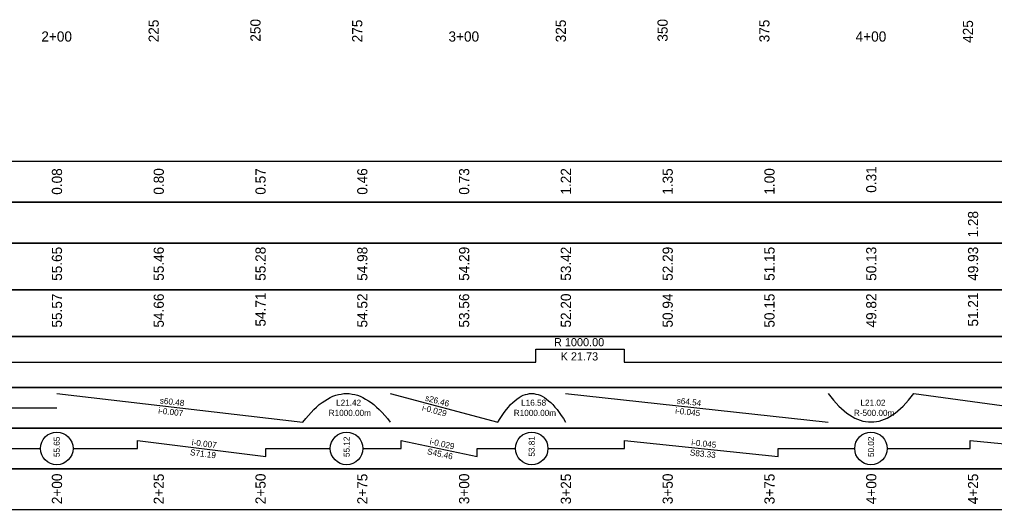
# Model space of a CAD drawing. Extents: x 655100 to 703495, y 6445581 to 6476602.
# Drawn here: x 669500.1 to 669739.6, y 6465749.1 to 6465869.5 of the extents above; entities that cross this region are included whole.
import ezdxf

# ---------------------------------------------------------------- set-up
doc = ezdxf.new("R2010")
doc.units = 0
for name, color, linetype in [('54', 7, 'Continuous'), ('Profile', 7, 'Continuous'), ('Profile Annotation', 7, 'Continuous'), ('Prop_Benching', 7, 'Continuous')]:
    doc.layers.add(name, color=color, linetype=linetype)

msp = doc.modelspace()

# ---------------------------------------------------------------- linework, layer by layer
at = {"layer": '54'}
for points in [[(669299.3, 6465824.57), (670219.3, 6465824.57), (670219.3, 6465834.57), (669299.3, 6465834.57)], [(669299.3, 6465814.57), (670219.3, 6465814.57), (670219.3, 6465824.57), (669299.3, 6465824.57)], [(669299.3, 6465803.07), (670219.3, 6465803.07), (670219.3, 6465814.57), (669299.3, 6465814.57)], [(669299.3, 6465791.57), (670219.3, 6465791.57), (670219.3, 6465803.07), (669299.3, 6465803.07)], [(669299.3, 6465779.07), (670219.3, 6465779.07), (670219.3, 6465791.57), (669299.3, 6465791.57)], [(669299.3, 6465769.07), (670219.3, 6465769.07), (670219.3, 6465779.07), (669299.3, 6465779.07)], [(669299.3, 6465759.07), (670219.3, 6465759.07), (670219.3, 6465769.07), (669299.3, 6465769.07)], [(669299.3, 6465749.07), (670219.3, 6465749.07), (670219.3, 6465759.07), (669299.3, 6465759.07)]]:
    msp.add_lwpolyline(points, close=True, dxfattribs=at)
for points in [[(669509.3, 6465834.57), (669509.3, 6465834.57)], [(669534.3, 6465834.57), (669534.3, 6465834.57)], [(669559.3, 6465834.57), (669559.3, 6465834.57)], [(669584.3, 6465834.57), (669584.3, 6465834.57)], [(669609.3, 6465834.57), (669609.3, 6465834.57)], [(669634.3, 6465834.57), (669634.3, 6465834.57)], [(669659.3, 6465834.57), (669659.3, 6465834.57)], [(669684.3, 6465834.57), (669684.3, 6465834.57)], [(669709.3, 6465834.57), (669709.3, 6465834.57)], [(669734.3, 6465834.57), (669734.3, 6465834.57)], [(669509.3, 6465824.57), (669509.3, 6465824.57)], [(669534.3, 6465824.57), (669534.3, 6465824.57)], [(669559.3, 6465824.57), (669559.3, 6465824.57)], [(669584.3, 6465824.57), (669584.3, 6465824.57)], [(669609.3, 6465824.57), (669609.3, 6465824.57)], [(669634.3, 6465824.57), (669634.3, 6465824.57)], [(669659.3, 6465824.57), (669659.3, 6465824.57)], [(669684.3, 6465824.57), (669684.3, 6465824.57)], [(669709.3, 6465824.57), (669709.3, 6465824.57)], [(669734.3, 6465824.57), (669734.3, 6465824.57)], [(669509.3, 6465814.57), (669509.3, 6465814.57)], [(669534.3, 6465814.57), (669534.3, 6465814.57)], [(669559.3, 6465814.57), (669559.3, 6465814.57)], [(669584.3, 6465814.57), (669584.3, 6465814.57)], [(669609.3, 6465814.57), (669609.3, 6465814.57)], [(669634.3, 6465814.57), (669634.3, 6465814.57)], [(669659.3, 6465814.57), (669659.3, 6465814.57)], [(669684.3, 6465814.57), (669684.3, 6465814.57)], [(669709.3, 6465814.57), (669709.3, 6465814.57)], [(669734.3, 6465814.57), (669734.3, 6465814.57)], [(669509.3, 6465803.07), (669509.3, 6465803.07)], [(669534.3, 6465803.07), (669534.3, 6465803.07)], [(669559.3, 6465803.07), (669559.3, 6465803.07)], [(669584.3, 6465803.07), (669584.3, 6465803.07)], [(669609.3, 6465803.07), (669609.3, 6465803.07)], [(669634.3, 6465803.07), (669634.3, 6465803.07)], [(669659.3, 6465803.07), (669659.3, 6465803.07)], [(669684.3, 6465803.07), (669684.3, 6465803.07)], [(669709.3, 6465803.07), (669709.3, 6465803.07)], [(669734.3, 6465803.07), (669734.3, 6465803.07)], [(669626.89, 6465791.57), (669626.89, 6465791.57)], [(669648.62, 6465791.57), (669648.62, 6465791.57)], [(669509.25, 6465779.07), (669509.25, 6465779.07)], [(669569.73, 6465779.07), (669569.73, 6465779.07)], [(669591.15, 6465779.07), (669591.15, 6465779.07)], [(669617.61, 6465779.07), (669617.61, 6465779.07)], [(669634.19, 6465779.07), (669634.19, 6465779.07)], [(669698.72, 6465779.07), (669698.72, 6465779.07)], [(669719.74, 6465779.07), (669719.74, 6465779.07)], [(669509.25, 6465769.07), (669509.25, 6465769.07)], [(669569.73, 6465769.07), (669569.73, 6465769.07)], [(669591.15, 6465769.07), (669591.15, 6465769.07)], [(669617.61, 6465769.07), (669617.61, 6465769.07)], [(669634.19, 6465769.07), (669634.19, 6465769.07)], [(669698.72, 6465769.07), (669698.72, 6465769.07)], [(669719.74, 6465769.07), (669719.74, 6465769.07)], [(669509.3, 6465759.07), (669509.3, 6465759.07)], [(669534.3, 6465759.07), (669534.3, 6465759.07)], [(669559.3, 6465759.07), (669559.3, 6465759.07)], [(669584.3, 6465759.07), (669584.3, 6465759.07)], [(669609.3, 6465759.07), (669609.3, 6465759.07)], [(669634.3, 6465759.07), (669634.3, 6465759.07)], [(669659.3, 6465759.07), (669659.3, 6465759.07)], [(669684.3, 6465759.07), (669684.3, 6465759.07)], [(669709.3, 6465759.07), (669709.3, 6465759.07)], [(669734.3, 6465759.07), (669734.3, 6465759.07)]]:
    msp.add_lwpolyline(points, dxfattribs=at)
at = {"layer": 'Profile Annotation'}
for points in [[(669309.3, 6465785.32), (669343.19, 6465785.32), (669343.19, 6465788.45), (669356.46, 6465788.45), (669356.46, 6465785.32), (669373.06, 6465785.32), (669373.06, 6465782.2), (669389.33, 6465782.2), (669389.33, 6465785.32), (669434.56, 6465785.32), (669434.56, 6465782.2), (669443.08, 6465782.2), (669443.08, 6465785.32), (669626.89, 6465785.32), (669626.89, 6465788.45), (669648.62, 6465788.45), (669648.62, 6465785.32), (669796.34, 6465785.32)], [(669509.25, 6465777.57), (669569.73, 6465770.57)], [(669569.73, 6465770.57), (669570.4, 6465771.42), (669571.07, 6465772.21), (669571.74, 6465772.95), (669572.4, 6465773.64), (669573.07, 6465774.26), (669573.74, 6465774.84), (669574.41, 6465775.36), (669575.08, 6465775.82), (669575.75, 6465776.23), (669576.42, 6465776.59), (669577.09, 6465776.89), (669577.76, 6465777.14), (669578.43, 6465777.33), (669579.1, 6465777.46), (669579.77, 6465777.55), (669581.11, 6465777.55), (669581.78, 6465777.46), (669582.45, 6465777.33), (669583.12, 6465777.14), (669583.78, 6465776.89), (669584.45, 6465776.59), (669585.12, 6465776.23), (669585.79, 6465775.82), (669586.46, 6465775.36), (669587.13, 6465774.84), (669587.8, 6465774.26), (669588.47, 6465773.64), (669589.14, 6465772.95), (669589.81, 6465772.21), (669590.48, 6465771.42), (669591.15, 6465770.57)], [(669591.15, 6465777.57), (669617.61, 6465770.57)], [(669617.61, 6465770.57), (669618.13, 6465771.42), (669618.64, 6465772.21), (669619.16, 6465772.95), (669619.68, 6465773.64), (669620.2, 6465774.26), (669620.72, 6465774.84), (669621.23, 6465775.36), (669621.75, 6465775.82), (669622.27, 6465776.23), (669622.79, 6465776.59), (669623.31, 6465776.89), (669623.83, 6465777.14), (669624.34, 6465777.33), (669624.86, 6465777.46), (669625.38, 6465777.55), (669626.42, 6465777.55), (669626.93, 6465777.46), (669627.45, 6465777.33), (669627.97, 6465777.14), (669628.49, 6465776.89), (669629.01, 6465776.59), (669629.53, 6465776.23), (669630.04, 6465775.82), (669630.56, 6465775.36), (669631.08, 6465774.84), (669631.6, 6465774.26), (669632.12, 6465773.64), (669632.63, 6465772.95), (669633.15, 6465772.21), (669633.67, 6465771.42), (669634.19, 6465770.57)], [(669634.19, 6465777.57), (669698.72, 6465770.57)], [(669698.72, 6465777.57), (669699.38, 6465776.73), (669700.04, 6465775.93), (669700.7, 6465775.19), (669701.35, 6465774.51), (669702.01, 6465773.88), (669702.67, 6465773.31), (669703.32, 6465772.79), (669703.98, 6465772.32), (669704.64, 6465771.91), (669705.29, 6465771.56), (669705.95, 6465771.26), (669706.61, 6465771.01), (669707.26, 6465770.82), (669707.92, 6465770.68), (669708.58, 6465770.6), (669709.89, 6465770.6), (669710.55, 6465770.68), (669711.21, 6465770.82), (669711.86, 6465771.01), (669712.52, 6465771.26), (669713.18, 6465771.56), (669713.83, 6465771.91), (669714.49, 6465772.32), (669715.15, 6465772.79), (669715.8, 6465773.31), (669716.46, 6465773.88), (669717.12, 6465774.51), (669717.77, 6465775.19), (669718.43, 6465775.93), (669719.09, 6465776.73), (669719.74, 6465777.57)], [(669719.74, 6465777.57), (669771.38, 6465770.57)], [(669470.34, 6465774.07), (669509.25, 6465774.07)], [(669466.4, 6465764.07), (669476.11, 6465764.07), (669476.11, 6465762.07), (669495.54, 6465766.07), (669495.54, 6465764.07), (669505.25, 6465764.07)], [(669513.25, 6465764.07), (669529.05, 6465764.07), (669529.05, 6465766.07), (669560.64, 6465762.07), (669560.64, 6465764.07), (669576.44, 6465764.07)], [(669584.44, 6465764.07), (669593.81, 6465764.07), (669593.81, 6465766.07), (669612.54, 6465762.07), (669612.54, 6465764.07), (669621.9, 6465764.07)], [(669629.9, 6465764.07), (669648.73, 6465764.07), (669648.73, 6465766.07), (669686.4, 6465762.07), (669686.4, 6465764.07), (669705.23, 6465764.07)], [(669713.23, 6465764.07), (669733.55, 6465764.07), (669733.55, 6465766.07), (669774.19, 6465762.07), (669774.19, 6465764.07), (669794.52, 6465764.07)]]:
    msp.add_lwpolyline(points, dxfattribs=at)
for centre in [(669509.25, 6465764.07), (669580.44, 6465764.07), (669625.9, 6465764.07), (669709.23, 6465764.07)]:
    msp.add_circle(centre, 4, dxfattribs=at)

# ---------------------------------------------------------------- texts
at = {"layer": 'Profile'}
for s, p in [('225', (669534.3, 6465863.89)), ('250', (669559.3, 6465864.05)), ('275', (669584.3, 6465863.89)), ('325', (669634.3, 6465863.89)), ('350', (669659.3, 6465864.05)), ('375', (669684.3, 6465863.89)), ('425', (669734.3, 6465863.76))]:
    msp.add_text(s, height=2.5, rotation=90, dxfattribs=at).set_placement(p)
for s, p in [('2+00', (669505.46, 6465864.07)), ('3+00', (669605.46, 6465864.07)), ('4+00', (669705.46, 6465864.07))]:
    msp.add_text(s, height=2.5, dxfattribs=at).set_placement(p)
at = {"layer": 'Profile Annotation'}
for s, height, rotation, p in [('0.08', 2.5, 90, (669510.55, 6465826.43)), ('0.80', 2.5, 90, (669535.55, 6465826.45)), ('0.57', 2.5, 90, (669560.55, 6465826.44)), ('0.46', 2.5, 90, (669585.55, 6465826.44)), ('0.73', 2.5, 90, (669610.55, 6465826.44)), ('1.22', 2.5, 90, (669635.55, 6465826.46)), ('1.35', 2.5, 90, (669660.55, 6465826.42)), ('1.00', 2.5, 90, (669685.55, 6465826.45)), ('0.31', 2.5, 90, (669710.55, 6465826.92)), ('1.28', 2.5, 90, (669735.55, 6465815.93)), ('55.65', 2.5, 90, (669510.55, 6465805.27)), ('55.46', 2.5, 90, (669535.55, 6465805.28)), ('55.28', 2.5, 90, (669560.55, 6465805.28)), ('54.98', 2.5, 90, (669585.55, 6465805.28)), ('54.29', 2.5, 90, (669610.55, 6465805.28)), ('53.42', 2.5, 90, (669635.55, 6465805.3)), ('52.29', 2.5, 90, (669660.55, 6465805.28)), ('51.15', 2.5, 90, (669685.55, 6465805.27)), ('50.13', 2.5, 90, (669710.55, 6465805.28)), ('49.93', 2.5, 90, (669735.55, 6465805.28)), ('55.57', 2.5, 90, (669510.55, 6465793.78)), ('54.66', 2.5, 90, (669535.55, 6465793.78)), ('54.71', 2.5, 90, (669560.55, 6465794.03)), ('54.52', 2.5, 90, (669585.55, 6465793.8)), ('53.56', 2.5, 90, (669610.55, 6465793.78)), ('52.20', 2.5, 90, (669635.55, 6465793.79)), ('50.94', 2.5, 90, (669660.55, 6465793.79)), ('50.15', 2.5, 90, (669685.55, 6465793.77)), ('49.82', 2.5, 90, (669710.55, 6465793.8)), ('51.21', 2.5, 90, (669735.55, 6465794.03)), ('s60.48', 1.5, 353.3978, (669534.5, 6465775.15)), ('s26.46', 1.5, 345.181, (669599.6, 6465775.85)), ('s64.54', 1.5, 353.8095, (669661.46, 6465775.12)), ('i-0.007', 1.5, 353.3978, (669534.12, 6465772.68)), ('i-0.029', 1.5, 345.181, (669598.86, 6465773.46)), ('i-0.045', 1.5, 353.8095, (669661.09, 6465772.64)), ('55.65', 1.5, 90, (669510, 6465761.96)), ('i-0.007', 1.5, 352.7848, (669542.34, 6465764.89)), ('55.12', 1.5, 90, (669581.19, 6465761.97)), ('i-0.029', 1.5, 347.9452, (669600.74, 6465765.1)), ('53.81', 1.5, 90, (669626.65, 6465762.08)), ('i-0.045', 1.5, 353.9378, (669665.04, 6465764.84)), ('50.02', 1.5, 90, (669709.98, 6465761.97)), ('S71.19', 1.5, 352.7848, (669541.93, 6465762.43)), ('S45.46', 1.5, 347.9452, (669600.13, 6465762.68)), ('S83.33', 1.5, 353.9378, (669664.69, 6465762.37)), ('2+00', 2.5, 90, (669510.55, 6465750.38)), ('2+25', 2.5, 90, (669535.55, 6465750.35)), ('2+50', 2.5, 90, (669560.55, 6465750.38)), ('2+75', 2.5, 90, (669585.55, 6465750.35)), ('3+00', 2.5, 90, (669610.55, 6465750.38)), ('3+25', 2.5, 90, (669635.55, 6465750.35)), ('3+50', 2.5, 90, (669660.55, 6465750.38)), ('3+75', 2.5, 90, (669685.55, 6465750.35)), ('4+00', 2.5, 90, (669710.55, 6465750.38)), ('4+25', 2.5, 90, (669735.55, 6465750.35))]:
    msp.add_text(s, height=height, rotation=rotation, dxfattribs=at).set_placement(p)
for s, p in [('L21.42', (669577.86, 6465774.57)), ('L16.58', (669623.31, 6465774.57)), ('L21.02', (669706.65, 6465774.57)), ('R1000.00m', (669576.05, 6465772.07)), ('R1000.00m', (669621.51, 6465772.07)), ('R-500.00m', (669705.04, 6465772.07))]:
    msp.add_text(s, height=1.5, dxfattribs=at).set_placement(p)
at = {"layer": 'Prop_Benching'}
for s, p in [('R 1000.00', (669631.37, 6465789.2)), ('K 21.73', (669633, 6465785.7))]:
    msp.add_text(s, height=2, dxfattribs=at).set_placement(p)

doc.saveas('drawing.dxf')
